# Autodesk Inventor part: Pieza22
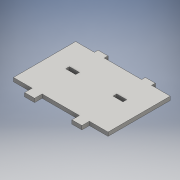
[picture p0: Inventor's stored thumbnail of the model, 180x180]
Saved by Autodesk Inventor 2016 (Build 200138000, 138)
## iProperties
Created: 2016-06
Part Number: Pieza22
Material: Genérico
Document SubType Name: Modeling
Designer: adm
Density: 1 g/cm^3
Appearance: Valor por defecto
Author: adm
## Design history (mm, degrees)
sketch "Boceto1"
  geometry: L1 (-38, -25)-(-38, 25); L2 (38, 25)-(38, -25); L3 (38, -25)-(-38, 25); L4 (-38, -25)-(38, 25); L5 (-15, 25)-(-15, 28); L6 (-15, 28)-(-23, 28); L7 (-23, 28)-(-23, 25); L8 (15, 25)-(15, 28); L9 (15, 28)-(23, 28); L10 (23, 28)-(23, 25); L11 (23, -31)-(23, -25); L12 (15, -25)-(15, -31); L13 (15, -31)-(23, -31); L14 (-15, -25)-(-15, -31); L15 (-23, -31)-(-23, -25); L16 (-15, -31)-(-23, -31); L17 (-38, 25)-(-23, 25); L18 (-15, 25)-(15, 25); L19 (23, 25)-(38, 25); L20 (-23, -25)-(-38, -25); L21 (38, -25)-(23, -25); L22 (15, -25)-(-15, -25); 1 further point
  constraints: 44 end point, 12 parallel, 5 horizontal, 4 vertical, 3 perpendicular, 2 horizontal alignment, 2 midpoint
  dimensions: "d0" = 50 distance of L2.start L2.end; "d1" = 76 distance of L2.end L1.start; "d2" = 30 distance between parallel lines of L8 L5; "d3" = 8 distance of L8.end L9.end; "d4" = 8 distance of L5.end L6.end; "d5" = 15 distance from line of point (0, 0) L8; "d6" = 3 distance of L8.start L8.end; "d7" = 3 distance of L5.start L5.end; "d16" = 6 distance of L14.start L14.end; "d17" = 6 distance of L12.start L12.end
extrude "Extrusión1" new body sketch "Boceto1" distance "d8" = 3; taper "d9" = 0 deg
sketch "Boceto2"
  geometry: L1 (-23, 5)-(-15, 5); L2 (-15, 5)-(-15, 2); L3 (-15, 2)-(-23, 2); L4 (-23, 2)-(-23, 5); L5 (-38, 25)-(-38, -25) reference; L6 (15, 25)-(-15, 25) reference; L7 (0, 0)-(0, 13.533); L8 (23, 5)-(15, 5); L9 (15, 5)-(15, 2); L10 (15, 2)-(23, 2); L11 (23, 2)-(23, 5)
  constraints: 18 end point, 4 symmetric about line, 2 parallel, 1 horizontal, 1 perpendicular, 1 vertical
  dimensions: "d10" = 8 distance of L2.end L3.end; "d11" = 15 distance between parallel lines of L5 L4; "d12" = 20 distance between parallel lines of L6 L1; "d13" = 3 distance of L1.end L2.end
extrude "Extrusión2" cut sketch "Boceto2" distance "d14" = 10; taper "d15" = 0 deg
node "Sólido1"
